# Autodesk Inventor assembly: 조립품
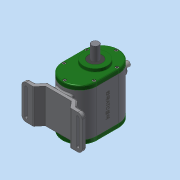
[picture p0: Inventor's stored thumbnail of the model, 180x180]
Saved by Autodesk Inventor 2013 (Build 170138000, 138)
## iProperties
Created: 2018-07
Part Number: 조립품
Document SubType Name: Assembly
Designer: dgall
Author: dgall
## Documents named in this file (14)
- C:\Users\dgall\Desktop\380707V1011\조립품.iam
- C:\Users\dgall\Desktop\380707V1011\본체.ipt
- C:\Users\dgall\Desktop\380707V1011\가변스프링.ipt
- C:\Users\dgall\Desktop\380707V1011\뒤커버.ipt
- C:\Users\dgall\Desktop\380707V1011\메인축.ipt
- C:\Users\dgall\Desktop\380707V1011\베어링 608.ipt
- C:\Users\dgall\Desktop\380707V1011\베어링 6003.ipt
- C:\Users\dgall\Desktop\380707V1011\볼트 M4.ipt
- C:\Users\dgall\Desktop\380707V1011\부시.ipt
- C:\Users\dgall\Desktop\380707V1011\서브축.ipt
- C:\Users\dgall\Desktop\380707V1011\슬라이더.ipt
- C:\Users\dgall\Desktop\380707V1011\앞커버.ipt
- C:\Users\dgall\Desktop\380707V1011\오일 실 8 22 7.ipt
- C:\Users\dgall\Desktop\380707V1011\오일 실 17 32 8.ipt
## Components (1 placed, 1 different names)
1. 가변스프링:1
